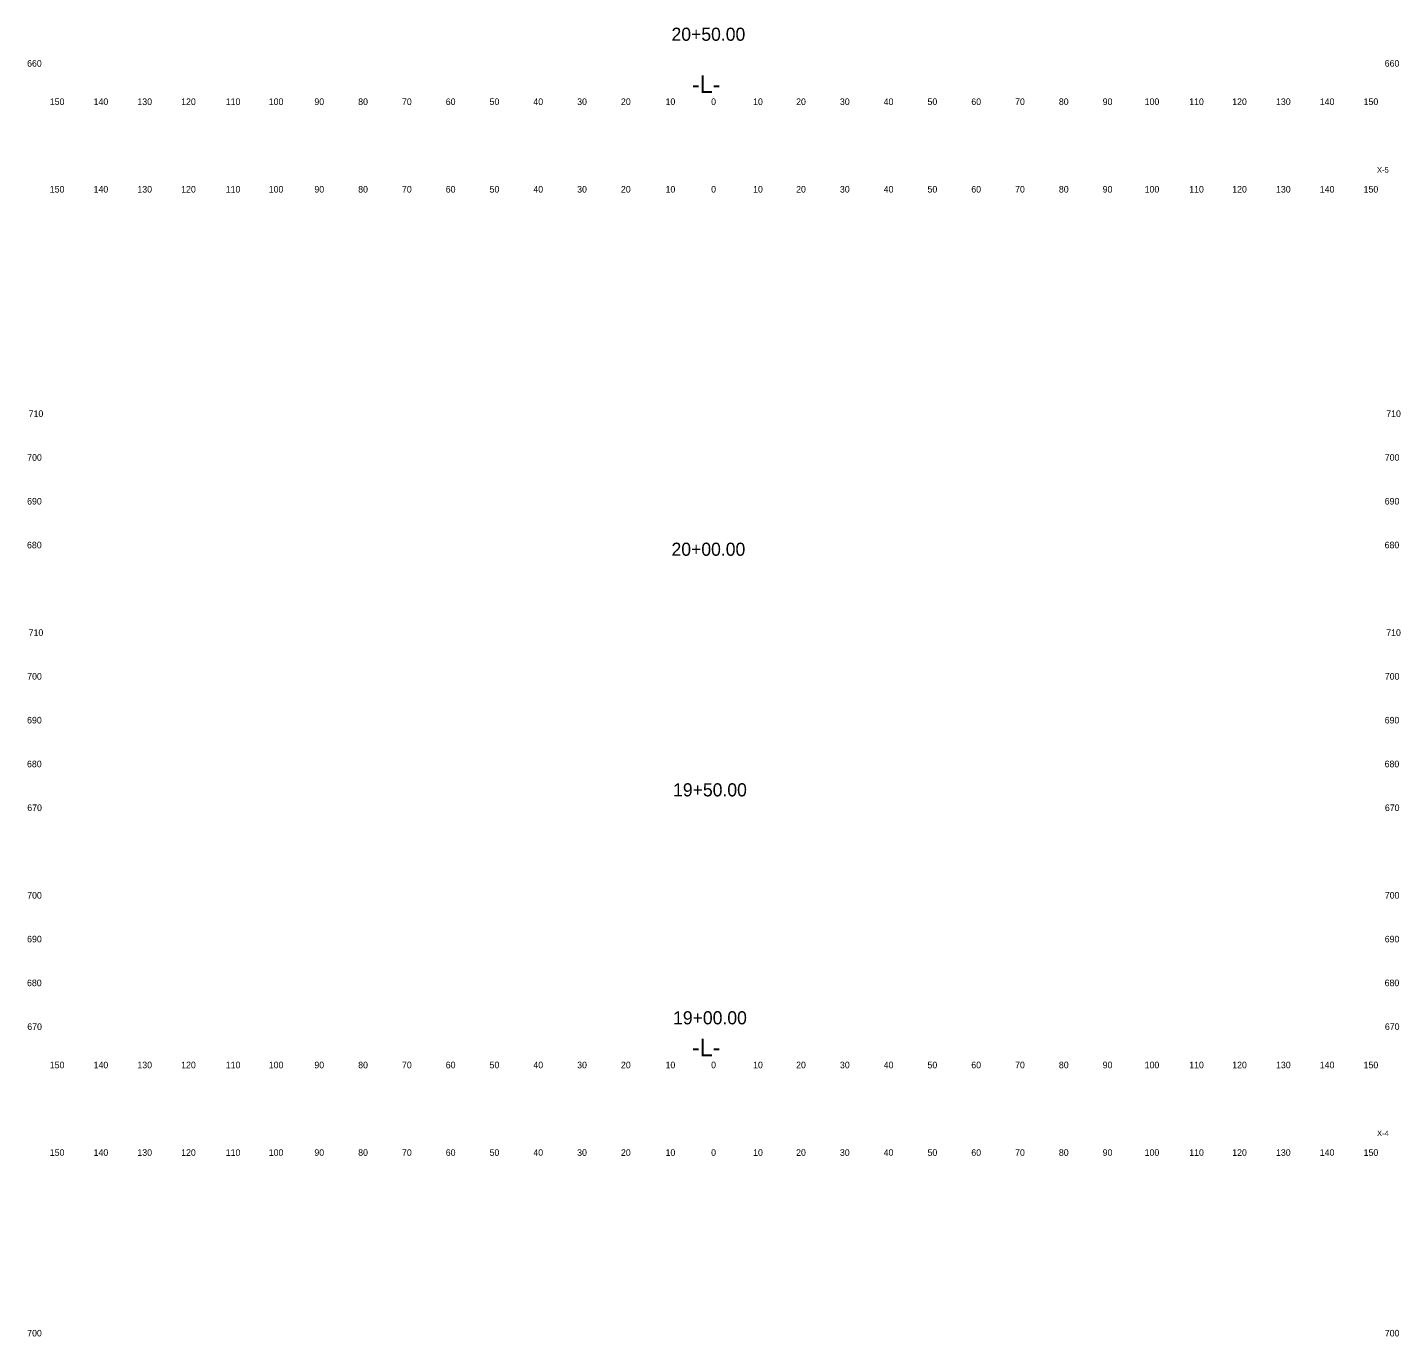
# Model space of a CAD drawing. Extents: x 3 to 317, y 0 to 2407.
# Drawn here: x 3.3 to 316.9, y 600 to 899 of the extents above; entities that cross this region are included whole.
import ezdxf

# ---------------------------------------------------------------- set-up
doc = ezdxf.new("R2010")
doc.units = 0
for name, color, linetype in [('Prop XS Ditch Standard Text', 7, 'Continuous'), ('Prop XS Dump Level', 7, 'Continuous'), ('Prop XS SE Text', 7, 'Continuous'), ('Prop XS Sheet Number', 7, 'Continuous'), ('Prop XS SS Elevation Text', 7, 'Continuous')]:
    doc.layers.add(name, color=color, linetype=linetype)

msp = doc.modelspace()

# ---------------------------------------------------------------- texts
at = {"layer": 'Prop XS Ditch Standard Text'}
for s, p in [('20+50.00', (150.41, 895.91)), ('20+00.00', (150.41, 778.29)), ('19+50.00', (150.77, 723.34)), ('19+00.00', (150.77, 671.28))]:
    msp.add_text(s, height=3, dxfattribs=at).set_placement(p)
at = {"layer": 'Prop XS Dump Level'}
for s, p in [('150', (8.44, 881.25)), ('140', (18.44, 881.25)), ('130', (28.44, 881.25)), ('120', (38.44, 881.25)), ('110', (48.62, 881.25)), ('100', (58.44, 881.25)), ('90', (68.86, 881.25)), ('80', (78.86, 881.25)), ('70', (88.86, 881.25)), ('60', (98.86, 881.25)), ('50', (108.86, 881.25)), ('40', (118.86, 881.25)), ('30', (128.86, 881.25)), ('20', (138.86, 881.25)), ('10', (149.04, 881.25)), ('0', (159.45, 881.25)), ('10', (169.04, 881.25)), ('20', (178.86, 881.25)), ('30', (188.86, 881.25)), ('40', (198.86, 881.25)), ('50', (208.86, 881.25)), ('60', (218.86, 881.25)), ('70', (228.86, 881.25)), ('80', (238.86, 881.25)), ('90', (248.86, 881.25)), ('100', (258.44, 881.25)), ('110', (268.62, 881.25)), ('120', (278.44, 881.25)), ('130', (288.44, 881.25)), ('140', (298.44, 881.25)), ('150', (308.44, 881.25)), ('150', (8.44, 861.25)), ('140', (18.44, 861.25)), ('130', (28.44, 861.25)), ('120', (38.44, 861.25)), ('110', (48.62, 861.25)), ('100', (58.44, 861.25)), ('90', (68.86, 861.25)), ('80', (78.86, 861.25)), ('70', (88.86, 861.25)), ('60', (98.86, 861.25)), ('50', (108.86, 861.25)), ('40', (118.86, 861.25)), ('30', (128.86, 861.25)), ('20', (138.86, 861.25)), ('10', (149.04, 861.25)), ('0', (159.45, 861.25)), ('10', (169.04, 861.25)), ('20', (178.86, 861.25)), ('30', (188.86, 861.25)), ('40', (198.86, 861.25)), ('50', (208.86, 861.25)), ('60', (218.86, 861.25)), ('70', (228.86, 861.25)), ('80', (238.86, 861.25)), ('90', (248.86, 861.25)), ('100', (258.44, 861.25)), ('110', (268.62, 861.25)), ('120', (278.44, 861.25)), ('130', (288.44, 861.25)), ('140', (298.44, 861.25)), ('150', (308.44, 861.25)), ('150', (8.44, 661.25)), ('140', (18.44, 661.25)), ('130', (28.44, 661.25)), ('120', (38.44, 661.25)), ('110', (48.62, 661.25)), ('100', (58.44, 661.25)), ('90', (68.86, 661.25)), ('80', (78.86, 661.25)), ('70', (88.86, 661.25)), ('60', (98.86, 661.25)), ('50', (108.86, 661.25)), ('40', (118.86, 661.25)), ('30', (128.86, 661.25)), ('20', (138.86, 661.25)), ('10', (149.04, 661.25)), ('0', (159.45, 661.25)), ('10', (169.04, 661.25)), ('20', (178.86, 661.25)), ('30', (188.86, 661.25)), ('40', (198.86, 661.25)), ('50', (208.86, 661.25)), ('60', (218.86, 661.25)), ('70', (228.86, 661.25)), ('80', (238.86, 661.25)), ('90', (248.86, 661.25)), ('100', (258.44, 661.25)), ('110', (268.62, 661.25)), ('120', (278.44, 661.25)), ('130', (288.44, 661.25)), ('140', (298.44, 661.25)), ('150', (308.44, 661.25)), ('150', (8.44, 641.25)), ('140', (18.44, 641.25)), ('130', (28.44, 641.25)), ('120', (38.44, 641.25)), ('110', (48.62, 641.25)), ('100', (58.44, 641.25)), ('90', (68.86, 641.25)), ('80', (78.86, 641.25)), ('70', (88.86, 641.25)), ('60', (98.86, 641.25)), ('50', (108.86, 641.25)), ('40', (118.86, 641.25)), ('30', (128.86, 641.25)), ('20', (138.86, 641.25)), ('10', (149.04, 641.25)), ('0', (159.45, 641.25)), ('10', (169.04, 641.25)), ('20', (178.86, 641.25)), ('30', (188.86, 641.25)), ('40', (198.86, 641.25)), ('50', (208.86, 641.25)), ('60', (218.86, 641.25)), ('70', (228.86, 641.25)), ('80', (238.86, 641.25)), ('90', (248.86, 641.25)), ('100', (258.44, 641.25)), ('110', (268.62, 641.25)), ('120', (278.44, 641.25)), ('130', (288.44, 641.25)), ('140', (298.44, 641.25)), ('150', (308.44, 641.25))]:
    msp.add_text(s, height=1.5, dxfattribs=at).set_placement(p)
at = {"layer": 'Prop XS SE Text'}
for s, p in [('660', (3.26, 890)), ('660', (313.26, 890)), ('710', (3.61, 810)), ('710', (313.61, 810)), ('700', (3.28, 800)), ('700', (313.28, 800)), ('690', (3.26, 790)), ('690', (313.26, 790)), ('680', (3.24, 780)), ('680', (313.24, 780)), ('710', (3.61, 760)), ('710', (313.61, 760)), ('700', (3.28, 750)), ('700', (313.28, 750)), ('690', (3.26, 740)), ('690', (313.26, 740)), ('680', (3.24, 730)), ('680', (313.24, 730)), ('670', (3.3, 720)), ('670', (313.3, 720)), ('700', (3.28, 700)), ('700', (313.28, 700)), ('690', (3.26, 690)), ('690', (313.26, 690)), ('680', (3.24, 680)), ('680', (313.24, 680)), ('670', (3.3, 670)), ('670', (313.3, 670)), ('700', (3.28, 600)), ('700', (313.28, 600))]:
    msp.add_text(s, height=1.5, dxfattribs=at).set_placement(p)
at = {"layer": 'Prop XS Sheet Number'}
for s, p in [('X-5', (311.5, 865.8)), ('X-4', (311.5, 645.77))]:
    msp.add_text(s, height=1.25, dxfattribs=at).set_placement(p)
at = {"layer": 'Prop XS SS Elevation Text'}
for p in [(155.06, 884), (155.06, 664)]:
    msp.add_text('-L-', height=4, dxfattribs=at).set_placement(p)

doc.saveas('drawing.dxf')
